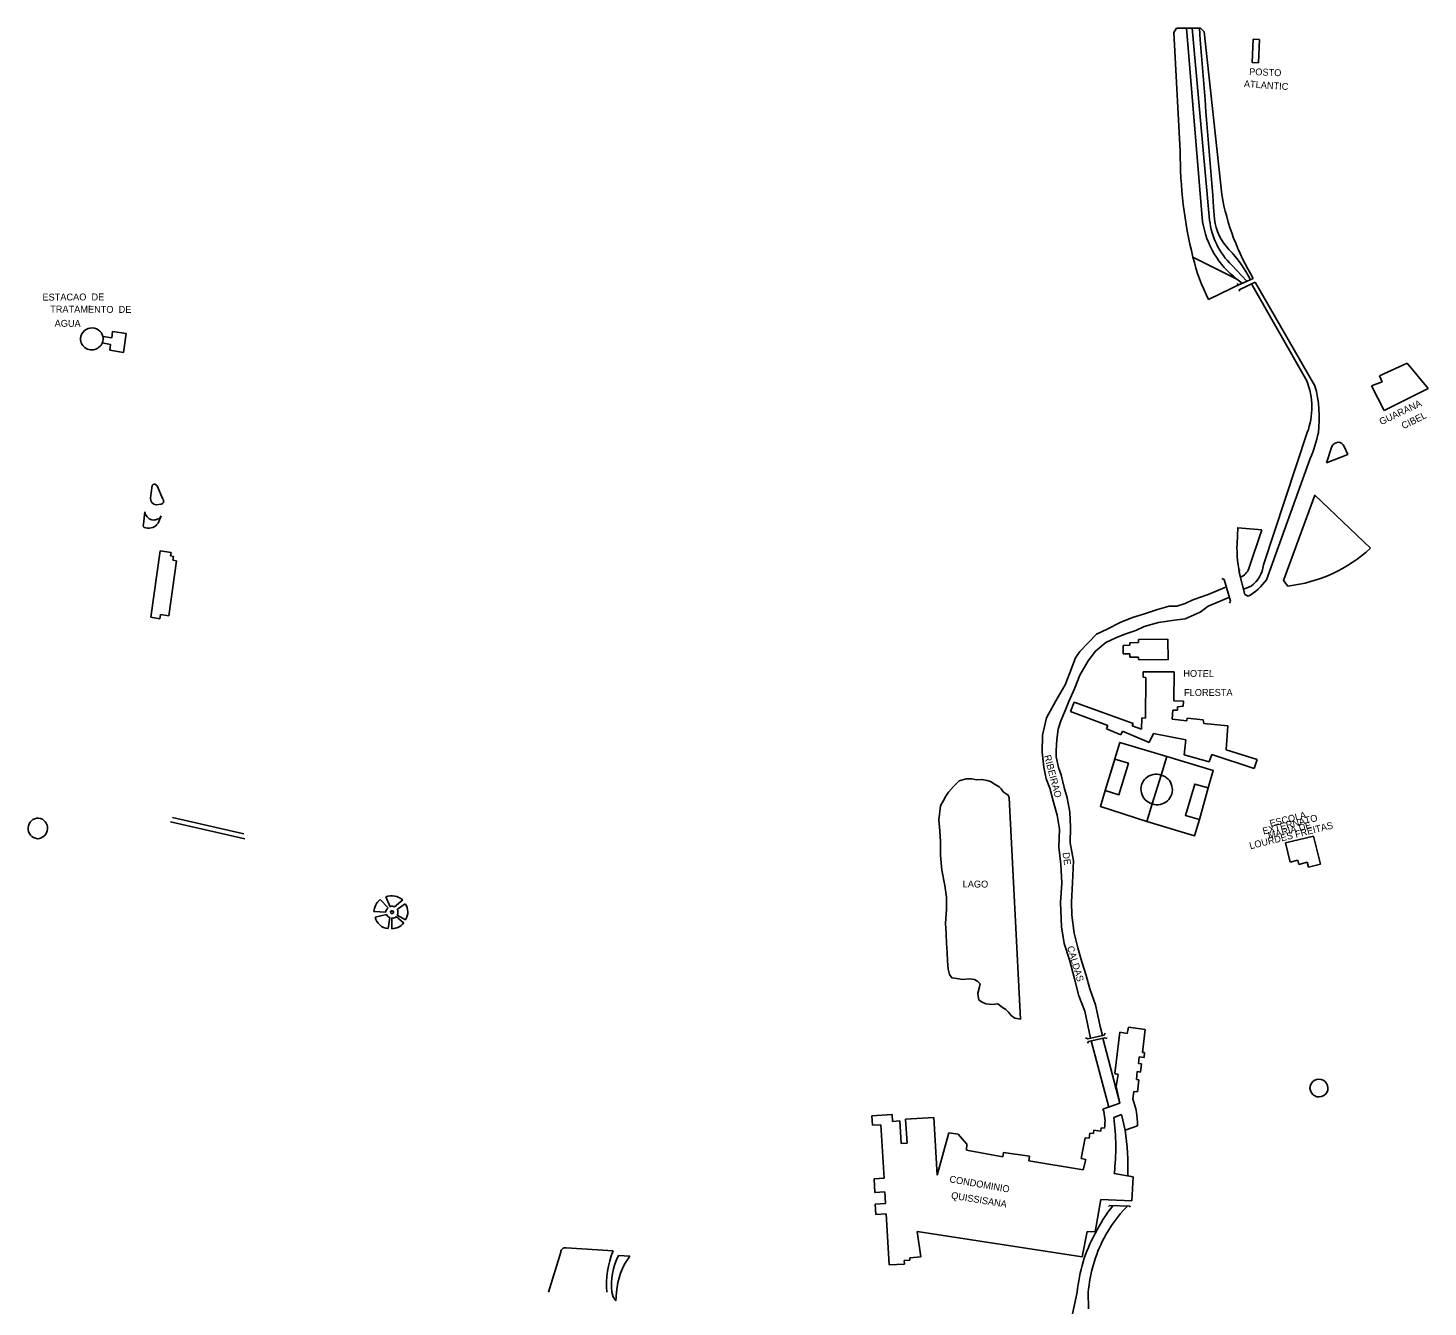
# Model space of a CAD drawing. Extents: x 325899 to 363134, y 7578590 to 7592502.
# Drawn here: x 338003 to 338817, y 7588493 to 7589237 of the extents above; entities that cross this region are included whole.
import ezdxf

# ---------------------------------------------------------------- set-up
doc = ezdxf.new("R2010")
doc.units = 0
for name, color, linetype in [('EDIFEXISTENT', 7, 'Continuous'), ('EDIFIDENTIF', 7, 'Continuous'), ('EDIFOBRAEXIS', 7, 'Continuous')]:
    doc.layers.add(name, color=color, linetype=linetype)

msp = doc.modelspace()

# ---------------------------------------------------------------- linework, layer by layer
at = {"layer": 'EDIFEXISTENT'}
for p, q in [((338669.42, 7589234.5), (338670.96, 7589237.05)), ((338670.96, 7589237.05), (338684.96, 7589237.19)), ((338684.96, 7589237.19), (338687.04, 7589234.88)), ((338715.12, 7589217.1), (338715.7, 7589230.62)), ((338715.7, 7589230.62), (338719.34, 7589230.42)), ((338719.34, 7589230.42), (338718.75, 7589216.87)), ((338718.75, 7589216.87), (338715.12, 7589217.1)), ((338715.69, 7589091.49), (338706.91, 7589087.71)), ((338707.44, 7589084.96), (338716.83, 7589089.42)), ((338706.91, 7589087.71), (338706.22, 7589088.63)), ((338707.62, 7589084.12), (338707.44, 7589084.96)), ((338046.59, 7589057.82), (338051.81, 7589056.99)), ((338051.81, 7589056.99), (338052.19, 7589060.59)), ((338052.19, 7589060.59), (338060.07, 7589059.58)), ((338060.07, 7589059.58), (338058.51, 7589048.44)), ((338051.09, 7589053.04), (338046.15, 7589054.05)), ((338050.63, 7589049.78), (338051.09, 7589053.04)), ((338058.51, 7589048.44), (338050.63, 7589049.78)), ((338789.18, 7589034.82), (338805.22, 7589042.32)), ((338805.22, 7589042.32), (338817.31, 7589027.47)), ((338790.57, 7589031.38), (338789.18, 7589034.82)), ((338784.37, 7589029.02), (338790.57, 7589031.38)), ((338791.72, 7589014.72), (338784.37, 7589029.02)), ((338817.31, 7589027.47), (338791.72, 7589014.72)), ((338074.56, 7588894.49), (338079.88, 7588933.11)), ((338079.88, 7588933.11), (338086.2, 7588932.24)), ((338089.39, 7588927.31), (338084.98, 7588895.36)), ((338086.2, 7588932.24), (338085.9, 7588930.11)), ((338085.9, 7588930.11), (338087.66, 7588929.87)), ((338087.66, 7588929.87), (338087.34, 7588927.59)), ((338087.34, 7588927.59), (338089.39, 7588927.31)), ((338707.42, 7588920.53), (338707.69, 7588922.07)), ((338710.78, 7588907.67), (338707.42, 7588920.53)), ((338697.34, 7588917.02), (338698.68, 7588916.35)), ((338698.68, 7588916.35), (338702.5, 7588903.78)), ((338702.5, 7588903.78), (338701.78, 7588902.6)), ((338712.71, 7588906.67), (338710.78, 7588907.67)), ((338079.78, 7588893.57), (338074.56, 7588894.49)), ((338080.12, 7588896.03), (338079.78, 7588893.57)), ((338084.98, 7588895.36), (338080.12, 7588896.03)), ((338640.01, 7588878.08), (338643.95, 7588878.16)), ((338640.07, 7588873.29), (338640.01, 7588878.08)), ((338643.83, 7588879.7), (338648.96, 7588879.76)), ((338643.95, 7588878.16), (338643.83, 7588879.7)), ((338648.96, 7588879.76), (338648.99, 7588881.49)), ((338648.99, 7588881.49), (338665.92, 7588881.7)), ((338665.92, 7588881.7), (338666.13, 7588869.78)), ((338643.85, 7588873.25), (338640.07, 7588873.29)), ((338643.85, 7588871.34), (338643.85, 7588873.25)), ((338648.86, 7588871.34), (338643.85, 7588871.34)), ((338648.89, 7588869.87), (338648.86, 7588871.34)), ((338666.13, 7588869.78), (338648.89, 7588869.87)), ((338651.62, 7588859.55), (338651.67, 7588862.69)), ((338651.67, 7588862.69), (338669.75, 7588862.69)), ((338669.75, 7588862.69), (338669.4, 7588845.85)), ((338653.24, 7588859.38), (338651.62, 7588859.55)), ((338652.97, 7588835.83), (338653.24, 7588859.38)), ((338609.31, 7588839.75), (338611.58, 7588845.01)), ((338611.58, 7588845.01), (338645.91, 7588832.72)), ((338669.4, 7588845.85), (338675.13, 7588845.63)), ((338675.13, 7588845.63), (338675, 7588842.69)), ((338631.14, 7588831.48), (338609.31, 7588839.75)), ((338668.98, 7588840.45), (338668.59, 7588835.3)), ((338671.54, 7588840.36), (338668.98, 7588840.45)), ((338671.61, 7588842.37), (338671.54, 7588840.36)), ((338675, 7588842.69), (338671.61, 7588842.37)), ((338630.27, 7588829.6), (338631.14, 7588831.48)), ((338638.71, 7588826.05), (338630.27, 7588829.6)), ((338645.91, 7588832.72), (338645.24, 7588831.37)), ((338645.24, 7588831.37), (338650.63, 7588829.3)), ((338650.63, 7588829.3), (338650.89, 7588835.89)), ((338650.89, 7588835.89), (338652.97, 7588835.83)), ((338668.59, 7588835.3), (338677.06, 7588834.19)), ((338677.06, 7588834.19), (338677.23, 7588835.76)), ((338677.23, 7588835.76), (338686.51, 7588834.73)), ((338686.51, 7588834.73), (338686.83, 7588832.68)), ((338686.83, 7588832.68), (338700.96, 7588831.38)), ((338700.96, 7588831.38), (338699.94, 7588817.3)), ((338639.68, 7588828.29), (338638.71, 7588826.05)), ((338655.06, 7588821.7), (338639.68, 7588828.29)), ((338657.61, 7588826.91), (338655.06, 7588821.7)), ((338676.42, 7588823.11), (338657.61, 7588826.91)), ((338675.54, 7588814.4), (338676.42, 7588823.11)), ((338690.02, 7588810.34), (338675.54, 7588814.4)), ((338691.64, 7588814.74), (338690.02, 7588810.34)), ((338716.23, 7588806.43), (338691.64, 7588814.74)), ((338699.94, 7588817.3), (338717.9, 7588811.69)), ((338717.9, 7588811.69), (338716.23, 7588806.43)), ((338734.34, 7588763.27), (338750.77, 7588767.19)), ((338750.77, 7588767.19), (338754.85, 7588750.97)), ((338737.15, 7588752.1), (338734.34, 7588763.27)), ((338741.61, 7588753.23), (338737.15, 7588752.1)), ((338742.23, 7588750.77), (338741.61, 7588753.23)), ((338747.03, 7588751.98), (338742.23, 7588750.77)), ((338747.74, 7588749.17), (338747.03, 7588751.98)), ((338754.85, 7588750.97), (338747.74, 7588749.17)), ((338618.17, 7588649.85), (338619.41, 7588649.28)), ((338619.41, 7588649.28), (338628.98, 7588651.42)), ((338619.8, 7588647.79), (338629.42, 7588649.93)), ((338628.98, 7588651.42), (338629.63, 7588652.54)), ((338629.42, 7588649.93), (338630.64, 7588649.53)), ((338635.11, 7588629.18), (338638.12, 7588653.08)), ((338638.12, 7588653.08), (338642.41, 7588652.35)), ((338642.41, 7588652.35), (338643.17, 7588656.05)), ((338643.17, 7588656.05), (338652.74, 7588654.75)), ((338652.74, 7588654.75), (338651.23, 7588641.39)), ((338619.23, 7588646.74), (338619.8, 7588647.79)), ((338651.23, 7588641.39), (338652.5, 7588641.25)), ((338649.3, 7588638.76), (338648.87, 7588634.97)), ((338648.87, 7588634.97), (338650.69, 7588634.76)), ((338652.18, 7588638.43), (338649.3, 7588638.76)), ((338650.69, 7588634.76), (338650.15, 7588629.98)), ((338652.5, 7588641.25), (338652.18, 7588638.43)), ((338637.19, 7588628.63), (338635.11, 7588629.18)), ((338635.84, 7588621.6), (338637.19, 7588628.63)), ((338648.22, 7588630.2), (338647.69, 7588625.57)), ((338647.69, 7588625.57), (338649.09, 7588625.41)), ((338650.15, 7588629.98), (338648.22, 7588630.2)), ((338649.09, 7588625.41), (338648.3, 7588618.37)), ((338637.99, 7588611.88), (338635.84, 7588621.6)), ((338646.15, 7588618.61), (338645.67, 7588614.37)), ((338648.3, 7588618.37), (338646.15, 7588618.61)), ((338628.25, 7588608.4), (338637.99, 7588611.88)), ((338493.9, 7588604.46), (338505.59, 7588605.19)), ((338494.24, 7588599), (338493.9, 7588604.46)), ((338505.59, 7588605.19), (338505.83, 7588601.24)), ((338505.83, 7588601.24), (338510.11, 7588601.51)), ((338510.11, 7588601.51), (338510.92, 7588588.43)), ((338513.44, 7588602.58), (338529.82, 7588603.59)), ((338514.31, 7588588.64), (338513.44, 7588602.58)), ((338529.82, 7588603.59), (338531.9, 7588569.92)), ((338639.12, 7588605.37), (338634.62, 7588603.6)), ((338641.26, 7588596.08), (338639.12, 7588605.37)), ((338499.14, 7588599.3), (338494.24, 7588599)), ((338501.07, 7588568.22), (338499.14, 7588599.3)), ((338531.9, 7588569.92), (338538.52, 7588594.52)), ((338538.52, 7588594.52), (338544.03, 7588593.9)), ((338544.03, 7588593.9), (338549.14, 7588588.03)), ((338620.27, 7588591.54), (338620.61, 7588594.47)), ((338620.61, 7588594.47), (338622.71, 7588594.23)), ((338622.71, 7588594.23), (338622.91, 7588596.08)), ((338622.91, 7588596.08), (338626.92, 7588595.63)), ((338626.92, 7588595.63), (338627.15, 7588597.61)), ((338627.15, 7588597.61), (338629.1, 7588597.39)), ((338648.29, 7588598.74), (338641.26, 7588596.08)), ((338510.92, 7588588.43), (338514.31, 7588588.64)), ((338549.14, 7588588.03), (338548.91, 7588584.55)), ((338548.91, 7588584.55), (338569.95, 7588580.73)), ((338615.66, 7588579.67), (338617.97, 7588591.8)), ((338617.97, 7588591.8), (338620.27, 7588591.54)), ((338569.95, 7588580.73), (338570.34, 7588583.27)), ((338570.34, 7588583.27), (338585.43, 7588581.09)), ((338585.43, 7588581.09), (338585.17, 7588578.3)), ((338585.17, 7588578.3), (338616.8, 7588573.11)), ((338618.23, 7588579.07), (338615.66, 7588579.67)), ((338616.8, 7588573.11), (338618.23, 7588579.07)), ((338495.12, 7588567.85), (338501.07, 7588568.22)), ((338634.86, 7588571.02), (338645.8, 7588569.12)), ((338645.8, 7588569.12), (338645.03, 7588555.14)), ((338495.61, 7588559.93), (338495.12, 7588567.85)), ((338501.43, 7588560.29), (338495.61, 7588559.93)), ((338501.85, 7588553.49), (338501.43, 7588560.29)), ((338495.74, 7588553.11), (338501.85, 7588553.49)), ((338496.11, 7588547.17), (338495.74, 7588553.11)), ((338627.1, 7588555.81), (338623.8, 7588537.08)), ((338645.03, 7588555.14), (338627.1, 7588555.81)), ((338631.49, 7588551.81), (338632.09, 7588552.34)), ((338632.09, 7588552.34), (338643.96, 7588551.89)), ((338643.96, 7588551.89), (338644.14, 7588551.41)), ((338502.13, 7588547.55), (338496.11, 7588547.17)), ((338503.97, 7588517.78), (338502.13, 7588547.55)), ((338616.19, 7588522.45), (338520.19, 7588537.26)), ((338520.19, 7588537.26), (338522.27, 7588522.57)), ((338618.98, 7588537.15), (338616.19, 7588522.45)), ((338623.8, 7588537.08), (338618.98, 7588537.15)), ((338516.02, 7588520.65), (338512.67, 7588520.38)), ((338512.67, 7588520.38), (338512.81, 7588518.3)), ((338522.27, 7588522.57), (338515.96, 7588521.84)), ((338515.96, 7588521.84), (338516.02, 7588520.65)), ((338512.81, 7588518.3), (338503.97, 7588517.78))]:
    msp.add_line(p, q, dxfattribs=at)
for centre, radius, start, end in [((338040.18, 7589056.17), 6.62, 14.44536, 182.95924), ((338040.12, 7589056.57), 6.59, 186.41912, 10.98549), ((338602.67, 7588599.12), 45.63, 359.52156, 19.5288), ((338608.25, 7588601.32), 21.21, 349.30475, 19.47262), ((338493.63, 7588586.27), 142.05, 353.83765, 7.00568)]:
    msp.add_arc(centre, radius, start, end, dxfattribs=at)
at = {"layer": 'EDIFOBRAEXIS'}
for points in [[(338676.88, 7589237.08), (338686.21, 7589124.51)], [(338680.12, 7589237.16), (338690.31, 7589125.48)], [(338673.2, 7589165.52), (338669.42, 7589234.5)], [(338687.04, 7589234.88), (338697.34, 7589140.29)], [(338706.15, 7589091.21), (338680.57, 7589103.93)], [(338703.23, 7589099.21), (338711.88, 7589089.87)], [(338706.15, 7589091.21), (338709.2, 7589088.74)], [(338716.83, 7589089.42), (338751.51, 7589029.03)], [(338689.67, 7589079.3), (338709.2, 7589088.74)], [(338746.8, 7589032.02), (338714.73, 7589088.42)], [(338721.66, 7588924.93), (338747.1, 7589001.91)], [(338758.26, 7588984.2), (338761.44, 7588993.72)], [(338768.64, 7588993.87), (338770.73, 7588989.1)], [(338748.86, 7588986.77), (338723.39, 7588916.3)], [(338770.73, 7588989.1), (338758.26, 7588984.2)], [(338074.75, 7588966.8), (338075.24, 7588971.18)], [(338078.07, 7588970.83), (338081.47, 7588963.17)], [(338074.32, 7588963.73), (338074.75, 7588966.8)], [(338080.46, 7588960.29), (338077.49, 7588959.95)], [(338735.84, 7588912.66), (338733.18, 7588915.91), (338751.47, 7588965.46), (338783.83, 7588934.68)], [(338070.11, 7588948.64), (338071.05, 7588955.79)], [(338080.54, 7588953.54), (338078.64, 7588949.26)], [(338706.24, 7588937.41), (338706.69, 7588946.51), (338720.62, 7588945.36)], [(338720.62, 7588945.36), (338713.16, 7588922.8)], [(338621.06, 7588649.72), (338617.66, 7588665.34), (338614.2, 7588674.32), (338611.73, 7588684.19), (338608.82, 7588695.3), (338605.64, 7588704.83), (338604.05, 7588714.36), (338603.53, 7588728.52), (338604.42, 7588739.81), (338603.74, 7588750.96), (338602.5, 7588760.84), (338602.97, 7588771.21), (338601.55, 7588779.44), (338599.57, 7588786.85), (338597.36, 7588795.13), (338595.22, 7588800.59), (338593.78, 7588807.27), (338592.86, 7588816.07), (338593.15, 7588825.85), (338595.5, 7588835.93), (338600.78, 7588845.83), (338606.24, 7588855.27), (338608.91, 7588862.18), (338612.33, 7588870.8), (338614.89, 7588874.47), (338619.8, 7588879.75), (338624.56, 7588884.65), (338630.72, 7588887.47), (338638.25, 7588891.5), (338645.38, 7588894.26), (338652.49, 7588896.44), (338660.05, 7588898.97), (338666.76, 7588900.92), (338671.3, 7588901), (338675.98, 7588902.55), (338680.07, 7588904.35), (338684.37, 7588906.03), (338689.35, 7588907.76), (338700.03, 7588912.09)], [(338709.99, 7588910.76), (338714.37, 7588912.51)], [(338701.76, 7588906.22), (338696.35, 7588903.9), (338689.52, 7588901.02), (338684.73, 7588897.39), (338676.04, 7588893.55), (338669.81, 7588892.7), (338660.56, 7588891.37), (338652.31, 7588889.09), (338647.36, 7588886.77), (338640.96, 7588884.55), (338635.65, 7588882.49), (338629.91, 7588879.86), (338623.86, 7588874.78), (338619.59, 7588869.12), (338614.85, 7588860.83), (338611.63, 7588852.85), (338608.41, 7588845.4), (338606.42, 7588840.69), (338603.69, 7588834.29), (338602.26, 7588829.34), (338601.48, 7588823.47), (338601.07, 7588816.8), (338600.99, 7588813.23), (338602.48, 7588807.13), (338604, 7588802.86), (338605.75, 7588795.51), (338607.36, 7588789.52), (338609.04, 7588781.06), (338609.35, 7588772.34), (338609.26, 7588763.27), (338611.05, 7588752.83), (338610.6, 7588740.1), (338610.04, 7588728.77), (338610.19, 7588721.27), (338611.58, 7588710.78), (338613.56, 7588702.3), (338615.87, 7588694.15), (338618.51, 7588686.11), (338620.67, 7588678.44), (338623.92, 7588668.98), (338625.28, 7588662.8), (338626.69, 7588656.5), (338628.02, 7588651.19)], [(338626.79, 7588784.47), (338629.58, 7588793.69), (338637.51, 7588791.29), (338643.03, 7588809.54), (338635.13, 7588811.93), (338629.58, 7588793.69), (338638.05, 7588821.68), (338665.32, 7588813.43), (338662.07, 7588802.7)], [(338656.87, 7588785.94), (338653.78, 7588775.72), (338626.79, 7588784.47), (338653.78, 7588775.72), (338681.44, 7588767.35), (338684.31, 7588776.81), (338676.24, 7588779.25), (338681.76, 7588797.49), (338689.36, 7588795.19), (338684.31, 7588776.81), (338689.36, 7588795.19), (338692.44, 7588805.38), (338665.32, 7588813.43)], [(338573.64, 7588789.52), (338580.3, 7588660.76), (338576.95, 7588661.37), (338574.93, 7588662.93), (338573.25, 7588664.87), (338571.67, 7588666.41), (338569.76, 7588667.59), (338567.16, 7588669.6), (338563.94, 7588669.35), (338560.06, 7588669.57), (338557.64, 7588670.8), (338556.11, 7588671.91), (338555.62, 7588674.01), (338555.51, 7588675.83), (338556.42, 7588679.46), (338556.79, 7588681.21), (338555.49, 7588682.58), (338553.5, 7588683.85), (338550.76, 7588684.24), (338546.43, 7588683.88), (338543.31, 7588684.32), (338540.34, 7588684.81), (338538.96, 7588686.7), (338538.17, 7588689.86), (338537.84, 7588694.68), (338537.6, 7588699.59), (338537.19, 7588705.02), (338537.13, 7588710.31), (338536.76, 7588716.57), (338537.26, 7588724.46), (338537.16, 7588731.74), (338536.33, 7588738.45), (338534.63, 7588747.44), (338533.83, 7588756.1), (338533.78, 7588763.78), (338533.36, 7588770.35), (338532.81, 7588776.68), (338533.67, 7588784.75), (338535.5, 7588787.93), (338536.8, 7588790.37), (338538.41, 7588792.71), (338541.25, 7588796.08), (338544.7, 7588799.37), (338548.65, 7588800.49), (338551.92, 7588800.56), (338554.79, 7588800.02), (338557.63, 7588800.17), (338560.83, 7588799.45), (338562.88, 7588798.91), (338565.61, 7588797.13), (338567.9, 7588795.92), (338569, 7588794.64), (338570.2, 7588793), (338573.1, 7588791.07), (338573.64, 7588789.52)], [(338656.87, 7588785.94), (338662.07, 7588802.7)], [(338085.95, 7588775.44), (338129.08, 7588765.56)], [(338087.01, 7588777.95), (338128.63, 7588768.6)], [(338213.58, 7588726.14), (338211.09, 7588731.86)], [(338211.13, 7588722.98), (338204.18, 7588723.41)], [(338207.8, 7588730.24), (338212.46, 7588725.41)], [(338221.05, 7588730.1), (338216.27, 7588726.07)], [(338217.89, 7588724.61), (338222.48, 7588727.83)], [(338204.99, 7588720.11), (338211.57, 7588721.61)], [(338213.44, 7588719.85), (338212.46, 7588713.41)], [(338214.61, 7588713.32), (338214.73, 7588719.64)], [(338217.2, 7588720.38), (338221.61, 7588716.62)], [(338222.67, 7588718.47), (338217.81, 7588721.14)], [(338628.26, 7588649.67), (338637.99, 7588611.88)], [(338621.42, 7588648.2), (338631.72, 7588609.58)], [(338315.99, 7588527.73), (338343.36, 7588525.9)], [(338305.7, 7588501.91), (338312.85, 7588525.28)], [(338346.44, 7588523.3), (338353.13, 7588522.95)], [(338345.38, 7588501.91), (338344.94, 7588496.87)], [(338613.28, 7588501.91), (338610.49, 7588489.31)], [(338619.87, 7588492.3), (338619.72, 7588501.91)]]:
    msp.add_lwpolyline(points, dxfattribs=at)
for centre, radius, start, end in [((428616.6, 7596356.82), 90213.66, 184.5264657, 184.5973253), ((338927.01, 7589164.66), 253.81, 179.80608, 193.84305), ((338837.5, 7589165.15), 142.35, 190.05805, 211.16073), ((338737.54, 7589132.62), 51.97, 188.97756, 232.83794), ((338732.71, 7589130.02), 42.65, 186.12052, 226.26657), ((338722, 7589128.9), 28.95, 185.77173, 225.0107), ((338647.45, 7589056.88), 74.7, 26.97095, 43.62066), ((338793.76, 7589131.76), 116.56, 193.81323, 206.74565), ((338707.53, 7589016.58), 42.2, 339.6595, 21.45474), ((338686.85, 7589010.6), 67.24, 352.579, 15.9101), ((338672.4, 7589018.59), 82.82, 337.40276, 348.38289), ((338765.07, 7588992.33), 3.89, 23.36457, 159.00344), ((338076.55, 7588970.12), 1.69, 24.95269, 141.02225), ((338077.81, 7588963.44), 3.5, 175.21995, 264.81546), ((338080.23, 7588961.99), 1.72, 277.75846, 43.68586), ((338076.15, 7588956.14), 5.11, 184.01438, 329.36915), ((338071.55, 7588948.05), 1.56, 157.9656, 271.41784), ((338073.27, 7588952.58), 6.31, 254.58942, 328.3012), ((338781.84, 7588934.95), 75.64, 178.14079, 193.18812), ((338726.59, 7588996.09), 83.95, 276.32751, 312.9869), ((338704.53, 7588926.22), 9.28, 293.26488, 338.35519), ((338703.14, 7588927.46), 18.69, 306.90614, 352.2318), ((338695.78, 7588936.2), 34.04, 299.82087, 324.21714), ((338659.14, 7588794.42), 8.78, 70.49216, 255.01745), ((338659.84, 7588794.2), 8.78, 250.22398, 75.28564), ((338009.06, 7588771.68), 6.04, 88.51877, 264.4316), ((338008.35, 7588771.73), 6.05, 271.17829, 81.77207), ((338214.52, 7588722.28), 10.18, 50.14547, 109.72109), ((338213.71, 7588722.73), 9.55, 128.17003, 175.89733), ((338213.99, 7588722.99), 2.86, 122.25393, 180.07671), ((338214.86, 7588723.55), 2.89, 60.76881, 116.28584), ((338214.77, 7588722.95), 0.856, 80.15338, 268.82849), ((338214.79, 7588722.95), 0.854, 267.35191, 81.62996), ((338213.43, 7588722.97), 4.75, 337.2958, 20.24794), ((338215, 7588722.99), 8.91, 329.43992, 32.88128), ((338213.14, 7588721.68), 8.3, 190.92008, 265.27007), ((338214.32, 7588722.64), 2.93, 200.6256, 252.59596), ((338214.47, 7588722.7), 9.38, 270.87777, 319.62073), ((338215.36, 7588722.01), 2.46, 255.20079, 318.38712), ((338753.79, 7588620.62), 5.12, 90.17661, 273.05266), ((338754.02, 7588620.63), 5.12, 270.3884, 92.84087), ((338452.88, 7588572.19), 189.89, 359.23418, 7.22835), ((338702.65, 7588497.32), 87.87, 141.30573, 153.87535), ((338699.86, 7588495.78), 80.29, 135.63058, 152.25947), ((338697.99, 7588494.55), 85.03, 150.81375, 175.03233), ((338315.56, 7588525.04), 2.73, 80.90571, 174.87409), ((338699.65, 7588495.64), 80.17, 152.09615, 175.5104), ((338391.91, 7588505.98), 52.47, 157.6907, 184.44572), ((338383.8, 7588505.39), 41.44, 154.38966, 184.81113), ((338383.38, 7588499.85), 38.06, 142.6383, 176.89712), ((338355.34, 7588504.98), 13.19, 193.45596, 217.97034)]:
    msp.add_arc(centre, radius, start, end, dxfattribs=at)

# ---------------------------------------------------------------- texts
at = {"layer": 'EDIFIDENTIF'}
for s, rotation, p in [('POSTO', 357.7705, (338713.22, 7589209.86)), ('ATLANTIC', 356.25015, (338710.14, 7589202.82)), ('ESTACAO  DE', 0.22211, (338011.43, 7589078.67)), ('TRATAMENTO  DE', 359.7324, (338015.9, 7589071.72)), ('AGUA', 359.32978, (338018.49, 7589063.5)), ('GUARANA', 25.4893, (338790.15, 7589006.17)), ('CIBEL', 26.27081, (338803.07, 7589003.78)), ('HOTEL', 359.377, (338674.98, 7588859.89)), ('FLORESTA', 0.17098, (338675.42, 7588848.7)), ('RIBEIRAO', 284.80531, (338593.97, 7588813.87)), ('ESCOLA', 14.14462, (338725.73, 7588772.45)), ('LOURDES FREITAS', 14.14462, (338713.98, 7588759.51)), ('EXTERNATO', 14.14462, (338721.67, 7588768.08)), ('MARIA DE', 14.14462, (338724.77, 7588765.53)), ('DE', 278.104, (338604.7, 7588757.48)), ('LAGO', 359.74177, (338546.64, 7588737.34)), ('CALDAS', 286.59999, (338607.3, 7588702.64)), ('CONDOMINIO', 350.08495, (338538.74, 7588565.91)), ('QUISSISANA', 350.62656, (338539.72, 7588556.4))]:
    msp.add_text(s, height=4, rotation=rotation, dxfattribs=at).set_placement(p)

doc.saveas('drawing.dxf')
